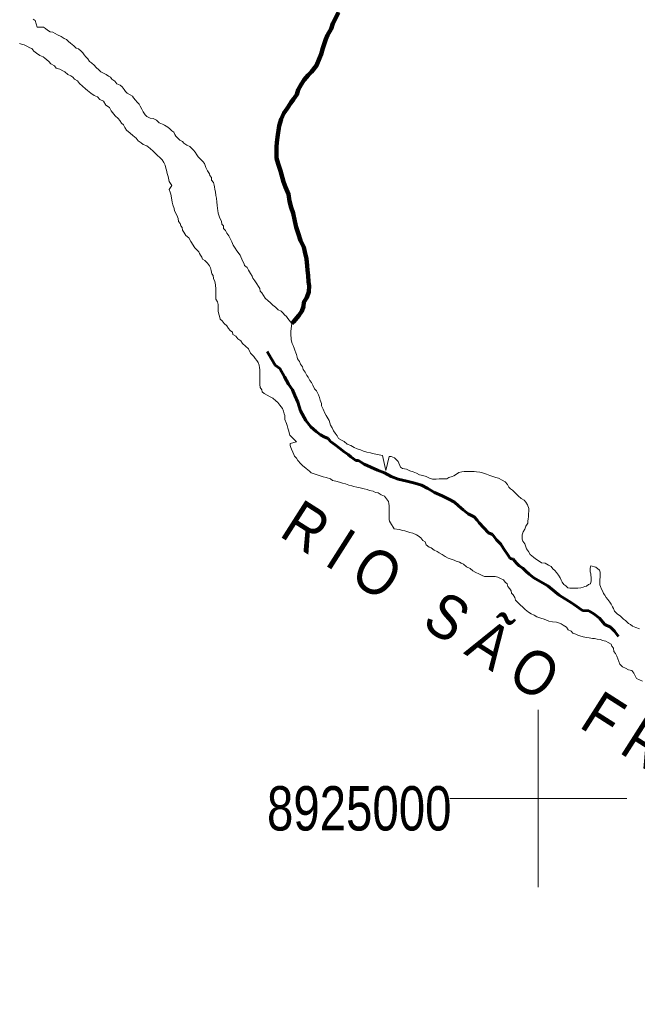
# Model space of a CAD drawing. Extents: x 553962 to 842807, y 8883888 to 9032388.
# Drawn here: x 644145 to 651119, y 8922767 to 8933785 of the extents above; entities that cross this region are included whole.
import ezdxf
from ezdxf.enums import TextEntityAlignment as Align

# ---------------------------------------------------------------- set-up
doc = ezdxf.new("R2010")
doc.units = 0
doc.header["$LTSCALE"] = 200
doc.linetypes.add('LONG_DASH_SHORT_DASH', pattern=[9.9, 6, -1.2, 1.5, -1.2])
for name, color, linetype, lineweight in [('2', 7, 'Continuous', 13), ('24', 7, 'Continuous', 25), ('25', 7, 'Continuous', 13), ('7', 7, 'Continuous', 90), ('9', 7, 'Continuous', 90)]:
    doc.layers.add(name, color=color, linetype=linetype, lineweight=lineweight)
for name, color, linetype in [('42', 7, 'Continuous'), ('47', 7, 'Continuous'), ('49', 7, 'Continuous')]:
    doc.layers.add(name, color=color, linetype=linetype)

msp = doc.modelspace()

# ---------------------------------------------------------------- linework, layer by layer
at = {"layer": '2'}
for p, q in [((650000, 8924000), (650000, 8926000)), ((649000, 8925000), (651000, 8925000))]:
    msp.add_line(p, q, dxfattribs=at)
at = {"layer": '24', "lineweight": 53}
msp.add_lwpolyline([(647745.8, 8933864.7), (647682.7, 8933739.9), (647662.4, 8933680), (647619.5, 8933610.1), (647601.8, 8933565.2), (647584, 8933507.7), (647568.8, 8933460.2), (647550.9, 8933395.3), (647530.7, 8933347.8), (647495.3, 8933265.4), (647439.9, 8933195.7), (647404.7, 8933158.3), (647359.4, 8933106), (647324.1, 8933053.6), (647291.3, 8932993.8), (647273.5, 8932938.8), (647235.8, 8932886.4), (647205.5, 8932846.6), (647167.7, 8932781.7), (647129.9, 8932729.3), (647097.1, 8932659.4), (647076.7, 8932584.5), (647056.1, 8932459.4), (647048.3, 8932399.4), (647045.5, 8932349.4), (647045.2, 8932271.8), (647047.4, 8932221.8), (647064.6, 8932156.6), (647091.8, 8932078.9), (647126.2, 8931956.1), (647148.4, 8931893.4), (647180.6, 8931815.7), (647192.7, 8931735.5), (647212.4, 8931665.4), (647232.1, 8931600.2), (647254.2, 8931512.5), (647268.9, 8931444.8), (647291.1, 8931374.7), (647315.7, 8931294.4), (647352.9, 8931216.7), (647365.1, 8931166.6), (647382.3, 8931086.4), (647391.9, 8931006.3), (647396.7, 8930958.7), (647401.4, 8930898.6), (647408.5, 8930828.5), (647413.3, 8930780.9), (647410.5, 8930713.4), (647387.7, 8930650.9), (647354.9, 8930598.5), (647349.7, 8930548.5), (647331.9, 8930496.1), (647296.6, 8930446.2), (647238.7, 8930376.4), (647217.5, 8930357.5)], dxfattribs=at)
at = {"layer": '25'}
for points in [[(644301.1, 8933790), (644323.4, 8933772.3), (644345.4, 8933699.6), (644415.4, 8933699.1), (644437.8, 8933683.9), (644460.2, 8933663.8), (644492.6, 8933646), (644522.5, 8933640.8)], [(644522.5, 8933640.8), (644547.4, 8933628.1), (644574.8, 8933612.9), (644614.7, 8933592.6), (644649.5, 8933569.9), (644674.5, 8933559.7), (644699.3, 8933537), (644721.7, 8933519.3), (644756.5, 8933489.1), (644786.3, 8933461.3), (644811.2, 8933453.6), (644841.1, 8933428.4), (644860.9, 8933408.2), (644875.7, 8933385.6), (644895.6, 8933363), (644915.4, 8933342.8), (644935.2, 8933312.6), (644957.6, 8933297.4), (644989.9, 8933267.2), (645007.2, 8933247.1), (645044.5, 8933214.3), (645064.4, 8933194.1), (645099.2, 8933176.3), (645124.2, 8933163.7), (645149, 8933146), (645171.5, 8933135.8), (645186.3, 8933113.2), (645221.2, 8933090.4), (645243.4, 8933060.2), (645280.8, 8933045), (645303.2, 8933024.8), (645325.5, 8932994.6), (645342.8, 8932974.4), (645360.2, 8932954.3), (645395.1, 8932936.6), (645420, 8932921.4), (645432.3, 8932901.3), (645454.6, 8932873.6), (645474.5, 8932853.4), (645496.8, 8932830.7), (645506.6, 8932808.1), (645526.4, 8932775.5), (645541.2, 8932742.8), (645563.4, 8932710.1), (645583.3, 8932690), (645618.1, 8932672.2), (645653.1, 8932669.5), (645690.5, 8932651.7), (645722.8, 8932621.4), (645760.2, 8932606.2), (645782.6, 8932593.5), (645820, 8932570.7), (645842.3, 8932550.6), (645864.7, 8932527.9), (645887.1, 8932512.7), (645899.4, 8932490.1), (645909.2, 8932470), (645929.1, 8932449.8), (645953.9, 8932424.6), (645983.8, 8932409.4), (645998.7, 8932389.3), (646033.5, 8932369), (646068.4, 8932353.8), (646090.8, 8932331.1), (646108.1, 8932311), (646128, 8932288.3), (646147.7, 8932258.1), (646162.6, 8932235.5), (646192.3, 8932205.2), (646214.7, 8932182.6), (646232, 8932162.4), (646249.2, 8932117.2), (646266.4, 8932077.1), (646288.7, 8932044.4), (646293.5, 8932024.3), (646313.4, 8932004.2), (646313.1, 8931974.1), (646332.9, 8931946.5), (646340.2, 8931916.4), (646345.1, 8931896.3), (646349.9, 8931868.7), (646357.2, 8931841.2), (646361.8, 8931801.1), (646366.6, 8931771), (646371.3, 8931725.9), (646376, 8931690.8), (646378.2, 8931653.2), (646383.1, 8931630.7), (646387.8, 8931600.6), (646400.1, 8931568), (646407.4, 8931545.4), (646424.7, 8931510.2), (646429.4, 8931477.7), (646446.8, 8931457.5), (646449, 8931427.5), (646468.9, 8931407.3), (646486.2, 8931374.6), (646508.4, 8931344.4), (646525.7, 8931306.8), (646542.9, 8931276.6), (646557.7, 8931241.5)], [(645677.7, 8932278.8), (645655.3, 8932301.4), (645620.5, 8932329.2), (645580.8, 8932359.5), (645540.9, 8932377.3), (645518.5, 8932395), (645483.6, 8932415.2), (645461.3, 8932445.4), (645424.1, 8932475.7), (645394.3, 8932503.4), (645354.5, 8932536.3), (645334.7, 8932566.4), (645317.4, 8932596.6), (645297.6, 8932616.7), (645277.8, 8932646.9), (645258, 8932669.6), (645225.7, 8932697.3), (645210.8, 8932717.5), (645181.1, 8932755.2), (645161.4, 8932792.9), (645119.1, 8932820.7), (645094.4, 8932863.4), (645052, 8932881.2), (645024.7, 8932911.5), (644987.3, 8932926.7), (644950, 8932954.5), (644912.7, 8932984.8), (644890.3, 8933002.5), (644855.6, 8933032.8), (644820.8, 8933063), (644798.5, 8933093.2), (644766.1, 8933113.5), (644746.3, 8933133.6), (644723.9, 8933148.8), (644691.5, 8933166.5), (644656.7, 8933196.8), (644634.3, 8933204.5), (644599.4, 8933224.7), (644559.5, 8933235), (644539.7, 8933262.7), (644499.8, 8933285.5), (644477.5, 8933310.6), (644432.8, 8933348.5), (644410.4, 8933363.7), (644375.5, 8933378.9), (644338.2, 8933406.7), (644305.8, 8933426.9), (644286, 8933457.1), (644263.6, 8933467.3), (644228.7, 8933485), (644198.8, 8933497.7), (644166.3, 8933505.5), (644143.9, 8933513.1)], [(647140.8, 8929317.4), (647133.5, 8929337.5), (647126.2, 8929367.6), (647113.9, 8929397.7), (647081.7, 8929435.5), (647059.4, 8929465.7), (647037, 8929485.8), (647004.7, 8929513.6), (646974.9, 8929531.3), (646940, 8929549.1), (646907.6, 8929566.8), (646885.2, 8929587), (646880.4, 8929607.1), (646860.6, 8929634.7), (646855.9, 8929669.8), (646856, 8929689.8), (646856.3, 8929729.9), (646856.6, 8929772.4), (646856.9, 8929810), (646857.1, 8929837.5), (646854.8, 8929857.6), (646850, 8929887.6), (646840.2, 8929917.8), (646825.4, 8929937.9), (646805.6, 8929963), (646790.7, 8929985.7), (646753.5, 8930021), (646728.8, 8930071.2), (646694.1, 8930101.5), (646661.8, 8930131.7), (646644.5, 8930161.9), (646609.6, 8930182.1), (646584.9, 8930212.3), (646552.5, 8930232.6), (646547.7, 8930260.2), (646522.8, 8930277.8), (646505.5, 8930300.5), (646485.7, 8930330.7), (646453.4, 8930358.4), (646431.1, 8930386.1), (646411.3, 8930406.3), (646404, 8930438.9), (646394.2, 8930461.5), (646386.9, 8930494.1), (646387.2, 8930524.1), (646387.3, 8930544.1), (646387.5, 8930569.2), (646380.2, 8930599.2), (646360.5, 8930631.9), (646360.6, 8930651.9), (646360.8, 8930672), (646361.3, 8930742.1), (646356.7, 8930792.2), (646349.5, 8930829.8), (646334.7, 8930862.4), (646330, 8930897.5), (646317.6, 8930917.6), (646307.9, 8930952.7), (646300.6, 8930985.3), (646288.3, 8931007.9), (646266, 8931038.1), (646236.2, 8931068.4), (646208.8, 8931083.6), (646201.5, 8931103.6), (646189.1, 8931126.2), (646176.8, 8931146.4), (646169.4, 8931166.4), (646124.8, 8931211.8), (646077.8, 8931279.7), (646055.6, 8931322.4), (646020.8, 8931350.2), (646001, 8931387.9), (645983.7, 8931410.5), (645981.4, 8931438.1), (645964.1, 8931458.2), (645959.3, 8931485.8), (645939.4, 8931505.9), (645937.2, 8931541), (645929.8, 8931561.1), (645912.6, 8931593.7), (645895.3, 8931628.9), (645890.5, 8931654), (645875.8, 8931696.6), (645868.5, 8931724.2), (645861.4, 8931774.3), (645854.2, 8931814.4), (645846.9, 8931839.5), (645834.6, 8931869.6), (645865, 8931914.5), (645832.8, 8931959.8), (645828.1, 8931994.9), (645823.2, 8932014.9), (645811, 8932050.1), (645803.8, 8932085.2), (645796.4, 8932107.7), (645789.2, 8932142.8), (645774.4, 8932173), (645754.6, 8932203.1), (645732.3, 8932223.3), (645697.5, 8932253.6), (645677.7, 8932278.8)], [(646557.7, 8931241.5), (646577.4, 8931206.3), (646599.7, 8931176.1), (646636.8, 8931128.3), (646661.4, 8931063.1), (646681.1, 8931030.4), (646683.5, 8931010.3), (646713.3, 8930987.6), (646730.6, 8930957.4), (646750.3, 8930922.3), (646772.6, 8930889.6), (646779.9, 8930867), (646802.2, 8930836.8), (646824.5, 8930804.1), (646841.8, 8930773.9), (646859.1, 8930751.3), (646861.3, 8930721.2), (646878.7, 8930701.1), (646898.5, 8930673.4), (646918.3, 8930643.3), (646953.1, 8930613), (646975.5, 8930595.3), (647005.2, 8930562.6), (647035.1, 8930542.3), (647064.9, 8930512.1), (647097.2, 8930494.4), (647119.6, 8930474.2), (647137, 8930454.1), (647156.8, 8930433.9), (647174.2, 8930413.7), (647218.7, 8930355.9), (647208.1, 8930270.8), (647207.9, 8930250.8), (647207.7, 8930218.2), (647210, 8930198.2), (647209.9, 8930175.7), (647214.7, 8930155.6), (647222, 8930133), (647231.9, 8930110.4), (647246.6, 8930077.8), (647254, 8930057.7), (647263.8, 8930027.6), (647271.1, 8930007.5), (647278.4, 8929977.4), (647280.7, 8929957.4), (647305.5, 8929927.2), (647317.8, 8929897.1), (647337.6, 8929866.9), (647347.3, 8929836.8), (647369.6, 8929806.6), (647386.9, 8929771.4), (647404.2, 8929751.3), (647421.4, 8929713.6), (647438.8, 8929691), (647456.1, 8929660.8), (647475.8, 8929620.6), (647495.6, 8929595.5), (647517.8, 8929552.8), (647532.5, 8929522.6), (647537.3, 8929492.5), (647552, 8929454.9), (647554.3, 8929427.3), (647574, 8929389.7), (647591.2, 8929347), (647606, 8929319.3), (647638.1, 8929264.1), (647655.2, 8929208.9), (647672.5, 8929178.7), (647689.7, 8929146.1), (647707, 8929118.4), (647729.3, 8929090.7), (647744.1, 8929060.6), (647779, 8929042.8), (647808.9, 8929027.6), (647841.2, 8928994.8), (647883.6, 8928982), (647920.9, 8928959.3), (647955.8, 8928944), (647993.3, 8928933.7), (648028.2, 8928918.5), (648065.6, 8928905.7), (648105.5, 8928897.9), (648128, 8928890.3), (648165.5, 8928882.5), (648205.4, 8928874.8), (648242.9, 8928869.5), (648277.9, 8928700.4), (648315.3, 8928856.5), (648340.3, 8928856.3), (648377.7, 8928841.1), (648417.4, 8928800.8), (648444.5, 8928735.5), (648466.8, 8928720.3), (648511.8, 8928712.5), (648549.2, 8928694.7), (648586.6, 8928684.5), (648624, 8928669.2), (648658.9, 8928651.4), (648696.3, 8928641.2), (648733.8, 8928630.9), (648771.1, 8928610.7)], [(649677.1, 8927362.9), (649654.8, 8927390.6), (649650, 8927420.7), (649627.6, 8927438.3), (649607.8, 8927466), (649575.4, 8927481.2), (649543, 8927496.5), (649513, 8927501.7), (649485.5, 8927501.9), (649445.5, 8927502.1), (649423, 8927502.3), (649393, 8927502.5), (649368.1, 8927515.2), (649328.2, 8927532.9), (649295.8, 8927548.2), (649260.9, 8927565.9), (649231.1, 8927593.7), (649188.7, 8927611.5), (649156.5, 8927641.7), (649131.5, 8927651.9), (649109.1, 8927664.6), (649074.2, 8927677.3), (649051.8, 8927687.5), (649016.8, 8927697.7), (648981.9, 8927710.5), (648949.5, 8927730.7), (648914.7, 8927751), (648882.3, 8927768.7), (648859.9, 8927786.4), (648825, 8927801.7), (648790.2, 8927826.9), (648767.7, 8927834.6), (648732.9, 8927862.3), (648723.2, 8927895), (648698.3, 8927907.6), (648676, 8927937.8), (648646.2, 8927960.6), (648623.7, 8927973.2), (648583.8, 8927991), (648548.9, 8928001.2), (648516.5, 8928011.5), (648494, 8928019.1), (648471.5, 8928021.8), (648431.6, 8928032.1), (648371.7, 8928042.5), (648332.1, 8928107.8), (648319.8, 8928127.9), (648317.4, 8928148), (648317.7, 8928183), (648317.9, 8928210.6), (648318.2, 8928245.6), (648318.4, 8928280.7), (648316.1, 8928300.7), (648313.8, 8928328.3), (648309, 8928348.3), (648286.7, 8928378.5), (648264.4, 8928411.2), (648227, 8928424), (648192.1, 8928446.7), (648162.2, 8928449.4), (648137.3, 8928464.6), (648094.8, 8928472.4), (648069.9, 8928485.1), (648034.9, 8928492.8), (647990, 8928503.2), (647952.5, 8928510.9), (647917.6, 8928518.7), (647895.1, 8928526.3), (647860.2, 8928534.1), (647825.2, 8928546.8), (647790.3, 8928554.6), (647755.4, 8928567.3), (647715.5, 8928580.1), (647678, 8928587.8), (647653.1, 8928603), (647605.7, 8928620.9), (647573.2, 8928626.1), (647538.3, 8928638.8), (647483.4, 8928656.7), (647438.5, 8928672), (647416.2, 8928689.7), (647378.9, 8928722.5), (647339.1, 8928755.3), (647319.3, 8928775.5), (647287, 8928810.7), (647269.7, 8928838.4), (647249.9, 8928861.1), (647242.5, 8928881.1), (647230.2, 8928906.2), (647215.5, 8928938.9), (647205.6, 8928959), (647200.8, 8928981.6), (647198.4, 8929001.6), (647271.1, 8929023.6), (647196.7, 8929099.2), (647179.6, 8929151.9), (647174.7, 8929174.5), (647167.5, 8929207.1), (647160.1, 8929227.2), (647140.5, 8929274.8), (647140.8, 8929317.4)], [(648771.1, 8928610.7), (648806.1, 8928602.9), (648826.1, 8928602.8), (648846.1, 8928602.6), (648881.2, 8928604.9), (648911.2, 8928604.7), (648948.7, 8928604.5), (648968.7, 8928604.3), (648988.8, 8928619.2), (649026.4, 8928631.5), (649046.5, 8928638.9), (649076.6, 8928658.7), (649101.8, 8928676.1), (649136.9, 8928683.3), (649161.9, 8928688.2), (649201.9, 8928687.9), (649236.9, 8928687.7), (649277, 8928687.4), (649301.9, 8928684.7), (649341.9, 8928679.5), (649369.4, 8928671.8), (649416.8, 8928656.4), (649454.2, 8928643.7), (649476.7, 8928636), (649519, 8928618.2), (649551.5, 8928613), (649591.3, 8928590.2), (649626.2, 8928569.9), (649651, 8928539.7), (649665.8, 8928509.6), (649688.2, 8928491.9), (649710.5, 8928476.8), (649742.8, 8928444), (649772.6, 8928413.8), (649804.9, 8928383.5), (649842.2, 8928363.2), (649859.6, 8928343.1), (649876.8, 8928310.4), (649894.1, 8928270.2), (649893.8, 8928240.2), (649891.1, 8928210.2), (649888.3, 8928177.7), (649885.7, 8928155.1), (649880.5, 8928127.6), (649880.3, 8928105.1), (649860, 8928070.2), (649847.3, 8928037.7), (649829.5, 8928005.3), (649819.3, 8927972.8), (649819, 8927942.8), (649818.9, 8927922.8), (649826.2, 8927902.7), (649848.5, 8927870), (649855.8, 8927849.9), (649865.6, 8927814.8), (649887.9, 8927784.6), (649907.6, 8927751.9), (649944.9, 8927721.6), (649967.3, 8927704), (649999.6, 8927683.7), (650037, 8927658.4), (650076.9, 8927653.2), (650116.8, 8927632.9), (650146.7, 8927617.7), (650164, 8927590), (650186.3, 8927569.8), (650203.7, 8927549.7), (650228.5, 8927519.5), (650248.3, 8927489.3), (650258.1, 8927461.7), (650270.4, 8927439.1), (650287.7, 8927413.9), (650310.1, 8927396.3), (650335, 8927376.1), (650357.4, 8927373.4), (650380, 8927373.3), (650405, 8927373.1), (650425, 8927373), (650447.5, 8927372.8), (650480, 8927375.1), (650505.1, 8927382.5), (650525.1, 8927389.8), (650545.2, 8927394.7), (650567.8, 8927412.1), (650590.4, 8927419.4), (650595.7, 8927454.5), (650595.8, 8927474.5), (650596, 8927494.5), (650593.6, 8927514.6), (650593.8, 8927534.6), (650583.9, 8927554.7), (650584.1, 8927577.2), (650584.2, 8927597.2), (650591.9, 8927622.2), (650649.4, 8927609.3), (650689.1, 8927574), (650699, 8927553.9), (650698.7, 8927521.4), (650698.5, 8927498.8), (650693.3, 8927466.3), (650693.1, 8927436.3)], [(650693.1, 8927436.3), (650695.4, 8927411.2), (650702.7, 8927391.2), (650712.5, 8927361.1), (650729.8, 8927333.4), (650734.6, 8927313.3), (650749.5, 8927293.2), (650766.8, 8927265.6), (650784.1, 8927242.9), (650808.9, 8927212.7), (650821.2, 8927190.1), (650836, 8927162.5), (650848.4, 8927142.3), (650860.7, 8927112.2), (650890.5, 8927082), (650927.8, 8927054.2), (650962.5, 8927023.9), (650984.9, 8927006.3), (651019.7, 8926973.5), (651042.1, 8926960.8), (651064.5, 8926943.1), (651101.9, 8926927.9), (651141.8, 8926912.6)], [(651177.3, 8926321.5), (651107.5, 8926352), (651078, 8926414.8), (651055.7, 8926445), (651018.2, 8926450.2), (650983.3, 8926470.5), (650950.9, 8926483.2), (650921.2, 8926516), (650908.9, 8926543.6), (650899.1, 8926573.7), (650886.8, 8926603.8), (650869.6, 8926636.5), (650852.2, 8926656.6), (650847.5, 8926694.2), (650830.2, 8926716.9), (650822.8, 8926742), (650788, 8926759.7), (650763.1, 8926774.9), (650725.6, 8926780.2), (650703.2, 8926792.8), (650665.7, 8926798.1), (650633.2, 8926805.8), (650613.2, 8926805.9), (650573.2, 8926811.2), (650545.8, 8926813.9), (650505.8, 8926821.7), (650468.4, 8926834.4), (650445.9, 8926842.1), (650423.5, 8926854.8), (650391.1, 8926862.5), (650371.2, 8926885.1), (650336.3, 8926902.9), (650316.6, 8926933.1), (650281.7, 8926953.3), (650259.3, 8926968.5), (650229.4, 8926981.2), (650207, 8926988.9), (650159.5, 8926991.7), (650119.5, 8926999.5), (650067.1, 8927022.3), (650029.7, 8927032.6), (649982.3, 8927047.9), (649952.4, 8927065.7), (649920, 8927080.9), (649887.7, 8927101.1), (649850.4, 8927131.4), (649830.5, 8927154.1), (649793.3, 8927186.9), (649773.4, 8927207.1), (649741.1, 8927237.3), (649736.3, 8927264.9), (649716.6, 8927295.1), (649699.2, 8927315.2), (649694.4, 8927342.8), (649677.1, 8927362.9)]]:
    msp.add_lwpolyline(points, dxfattribs=at)
at = {"layer": '7', "linetype": 'LONG_DASH_SHORT_DASH', "lineweight": 60}
for points in [[(647971.9, 8928809.9), (647942, 8928812.6), (647912.1, 8928835.3), (647884.7, 8928852.9), (647854.9, 8928878.1), (647807.6, 8928908.4), (647755.4, 8928951.2), (647708.1, 8928989), (647655.9, 8929026.8), (647628.6, 8929059.5), (647583.7, 8929077.2), (647543.9, 8929100), (647491.7, 8929140.3), (647434.5, 8929190.6), (647375, 8929263.5), (647315.7, 8929371.4), (647286.4, 8929469.2), (647251.9, 8929544.4), (647224.8, 8929609.6), (647180.2, 8929672.4), (647135.8, 8929755.2), (647081.4, 8929850.6), (647031.7, 8929885.9), (646955.1, 8930016.4), (646941, 8930039.5)], [(650905.5, 8926825.8), (650861.5, 8926885.3), (650814.4, 8926933.1), (650752.1, 8926963.5), (650692.5, 8927033.8), (650627.8, 8927081.7), (650570.6, 8927117.1), (650500.6, 8927119.9), (650398.6, 8927193.1), (650373.7, 8927205.7), (650236.8, 8927291.5), (650194.5, 8927326.8), (650107.5, 8927397.3), (650022.8, 8927445.3), (649950.6, 8927488.2), (649895.8, 8927528.5), (649861.1, 8927563.7), (649823.8, 8927596.5), (649784, 8927624.2), (649754.2, 8927654.4), (649717, 8927697.1), (649682.1, 8927707.3), (649664.8, 8927737.4), (649607.8, 8927817.8), (649578.1, 8927868), (649528.5, 8927915.8), (649481.4, 8927976.1), (649439, 8927996.4), (649332.2, 8928109.6), (649309.9, 8928137.2), (649277.7, 8928177.4), (649210.4, 8928210.3), (649150.7, 8928255.7), (649101, 8928298.5), (649053.8, 8928341.2), (648989, 8928374.1), (648916.8, 8928414.6), (648829.6, 8928452.5), (648752.3, 8928495.5), (648680.1, 8928533.4), (648607.8, 8928556.3), (648515.4, 8928579.3), (648418.1, 8928602.4), (648338.2, 8928630.3), (648263.5, 8928670.7), (648186.2, 8928703.7), (648109, 8928736.6), (648034.2, 8928772.1), (648004.3, 8928787.2), (647971.9, 8928809.9)]]:
    msp.add_lwpolyline(points, dxfattribs=at)
at = {"layer": '9'}
msp.add_lwpolyline([(647745.8, 8933864.7), (647682.7, 8933739.9), (647662.4, 8933680), (647619.5, 8933610.1), (647601.8, 8933565.2), (647584, 8933507.7), (647568.8, 8933460.2), (647550.9, 8933395.3), (647530.7, 8933347.8), (647495.3, 8933265.4), (647439.9, 8933195.7), (647404.7, 8933158.3), (647359.4, 8933106), (647324.1, 8933053.6), (647291.3, 8932993.8), (647273.5, 8932938.8), (647235.8, 8932886.4), (647205.5, 8932846.6), (647167.7, 8932781.7), (647129.9, 8932729.3), (647097.1, 8932659.4), (647076.7, 8932584.5), (647056.1, 8932459.4), (647048.3, 8932399.4), (647045.5, 8932349.4), (647045.2, 8932271.8), (647047.4, 8932221.8), (647064.6, 8932156.6), (647091.8, 8932078.9), (647126.2, 8931956.1), (647148.4, 8931893.4), (647180.6, 8931815.7), (647192.7, 8931735.5), (647212.4, 8931665.4), (647232.1, 8931600.2), (647254.2, 8931512.5), (647268.9, 8931444.8), (647291.1, 8931374.7), (647315.7, 8931294.4), (647352.9, 8931216.7), (647365.1, 8931166.6), (647382.3, 8931086.4), (647391.9, 8931006.3), (647396.7, 8930958.7), (647401.4, 8930898.6), (647408.5, 8930828.5), (647413.3, 8930780.9), (647410.5, 8930713.4), (647387.7, 8930650.9), (647354.9, 8930598.5), (647349.7, 8930548.5), (647331.9, 8930496.1), (647296.6, 8930446.2), (647238.7, 8930376.4), (647217.5, 8930357.5)], dxfattribs=at)

# ---------------------------------------------------------------- texts
at = {"layer": '42'}
msp.add_text('S  E  R  G  I  P  E', height=2000, rotation=329.237, dxfattribs=at).set_placement((637761.3, 8923891.3))
at = {"layer": '47', "width": 0.8}
msp.add_text('8925000', height=500, dxfattribs=at).set_placement((647979.3, 8924638.8), align=Align.CENTER)
at = {"layer": '49', "width": 0.9}
msp.add_text('R I O   S Ã O   F R A N C I S C O', height=500, rotation=327.505, dxfattribs=at).set_placement((647062, 8927967.9))

doc.saveas('drawing.dxf')
